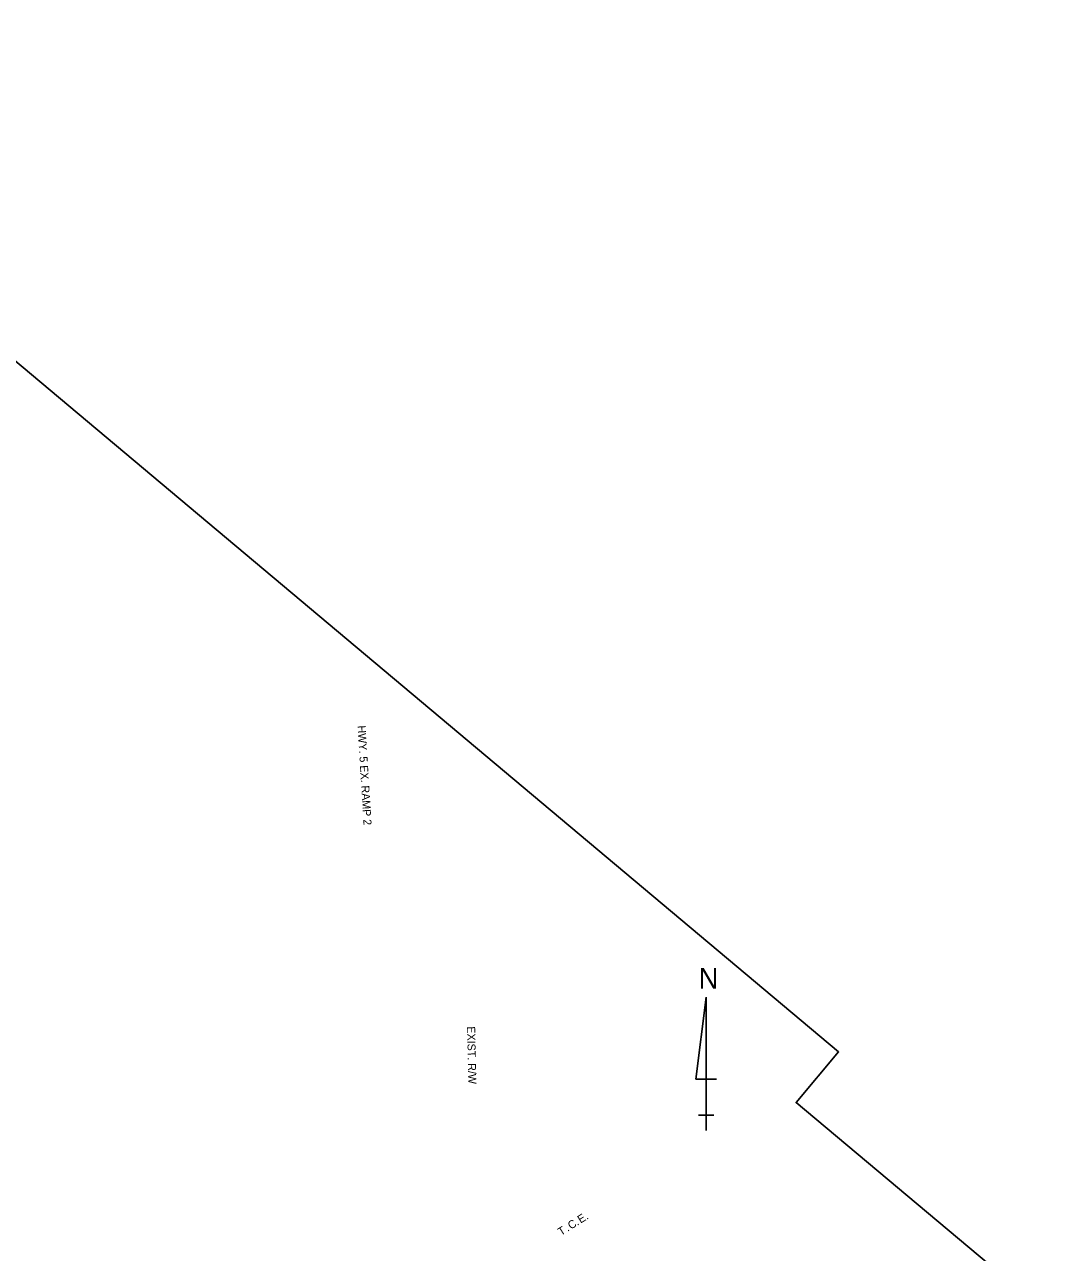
# Model space of a CAD drawing. Extents: x 1292584 to 1294692, y 222754 to 224578.
# Drawn here: x 1293562 to 1294340, y 223658 to 224578 of the extents above; entities that cross this region are included whole.
import ezdxf

# ---------------------------------------------------------------- set-up
doc = ezdxf.new("R2010")
doc.units = 0
for name, color, linetype in [('1', 7, 'Continuous'), ('R_Striping', 7, 'Continuous'), ('S_FIBER_OPTIC_CABLE_ANNOT', 7, 'Continuous'), ('S_SURVEY_TEXT_ANNOT', 7, 'Continuous')]:
    doc.layers.add(name, color=color, linetype=linetype)

msp = doc.modelspace()

# ---------------------------------------------------------------- linework, layer by layer
at = {"layer": '1'}
msp.add_lwpolyline([(1292584.05, 223779.83), (1293254.04, 224578.3), (1294171.77, 223808.23), (1294139.92, 223770.28), (1294291.79, 223642.84), (1294281.83, 223630.97), (1294336.68, 223584.95), (1294241.87, 223471.95), (1294339.54, 223390), (1293806.17, 222754.35)], close=True, dxfattribs=at)
msp.add_lwpolyline([(1292584.05, 223779.83), (1293254.04, 224578.3), (1294171.77, 223808.23), (1294139.92, 223770.28), (1294291.79, 223642.84), (1294281.83, 223630.97), (1294336.68, 223584.95), (1294241.87, 223471.95), (1294339.54, 223390), (1293806.17, 222754.35)], close=True, dxfattribs=at)
msp.add_lwpolyline([(1292584.05, 223779.83), (1293254.04, 224578.3), (1294171.77, 223808.23), (1294139.92, 223770.28), (1294291.79, 223642.84), (1294281.83, 223630.97), (1294336.68, 223584.95), (1294241.87, 223471.95), (1294339.54, 223390), (1293806.17, 222754.35)], close=True, dxfattribs=at)
msp.add_lwpolyline([(1292584.05, 223779.83), (1293254.04, 224578.3), (1294171.77, 223808.23), (1294139.92, 223770.28), (1294291.79, 223642.84), (1294281.83, 223630.97), (1294336.68, 223584.95), (1294241.87, 223471.95), (1294339.54, 223390), (1293806.17, 222754.35)], close=True, dxfattribs=at)
msp.add_lwpolyline([(1292584.05, 223779.83), (1293254.04, 224578.3), (1294171.77, 223808.23), (1294139.92, 223770.28), (1294291.79, 223642.84), (1294281.83, 223630.97), (1294336.68, 223584.95), (1294241.87, 223471.95), (1294339.54, 223390), (1293806.17, 222754.35)], close=True, dxfattribs=at)
msp.add_lwpolyline([(1292584.05, 223779.83), (1293254.04, 224578.3), (1294171.77, 223808.23), (1294139.92, 223770.28), (1294291.79, 223642.84), (1294281.83, 223630.97), (1294336.68, 223584.95), (1294241.87, 223471.95), (1294339.54, 223390), (1293806.17, 222754.35)], close=True, dxfattribs=at)
at = {"layer": 'S_SURVEY_TEXT_ANNOT'}
for p, q in [((1294072.48, 223849.34), (1294064.78, 223787.8)), ((1294072.48, 223749.34), (1294072.48, 223849.34)), ((1294072.48, 223849.34), (1294072.48, 223772.42)), ((1294064.78, 223787.8), (1294080.17, 223787.8)), ((1294072.48, 223749.34), (1294072.48, 223772.42)), ((1294072.48, 223760.88), (1294066.71, 223760.88)), ((1294066.71, 223760.88), (1294078.24, 223760.88)), ((1294072.48, 223749.34), (1294072.48, 223760.88))]:
    msp.add_line(p, q, dxfattribs=at)

# ---------------------------------------------------------------- texts
at = {"layer": 'R_Striping'}
for s, rotation, p in [('HWY. 5 EX. RAMP 2', 273.49613, (1293811.24, 224052.73)), ('C', 32.15368, (1293971.15, 223674.92)), ('E', 32.15368, (1293978.43, 223679.5)), ('.', 32.15368, (1293975.95, 223677.94)), ('.', 32.15368, (1293982.99, 223682.36)), ('T', 32.15368, (1293963.71, 223670.24)), ('.', 32.15368, (1293968.67, 223673.36))]:
    msp.add_text(s, height=6, rotation=rotation, dxfattribs=at).set_placement(p)
at = {"layer": 'S_FIBER_OPTIC_CABLE_ANNOT'}
msp.add_text('EXIST. R/W', height=6, rotation=271.19347, dxfattribs=at).set_placement((1293893.37, 223827.34))
at = {"layer": 'S_SURVEY_TEXT_ANNOT'}
msp.add_text('N', height=15.38, rotation=360, dxfattribs=at).set_placement((1294066.84, 223855.75))

doc.saveas('drawing.dxf')
